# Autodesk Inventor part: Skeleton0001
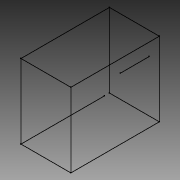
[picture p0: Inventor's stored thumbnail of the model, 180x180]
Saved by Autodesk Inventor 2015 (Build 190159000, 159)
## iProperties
Created: 2007-02
Part Number: Skeleton0001
Document SubType Name: Modeling
Designer: Autodesk, Inc.
Density: 1 g/cm^3
Material: Generic
Appearance: Default
_SkeletonDoc: Frame Skeleton File
_Version: 15.0.0
Author: Autodesk, Inc.
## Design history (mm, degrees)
sketch "Reference Skeleton"
